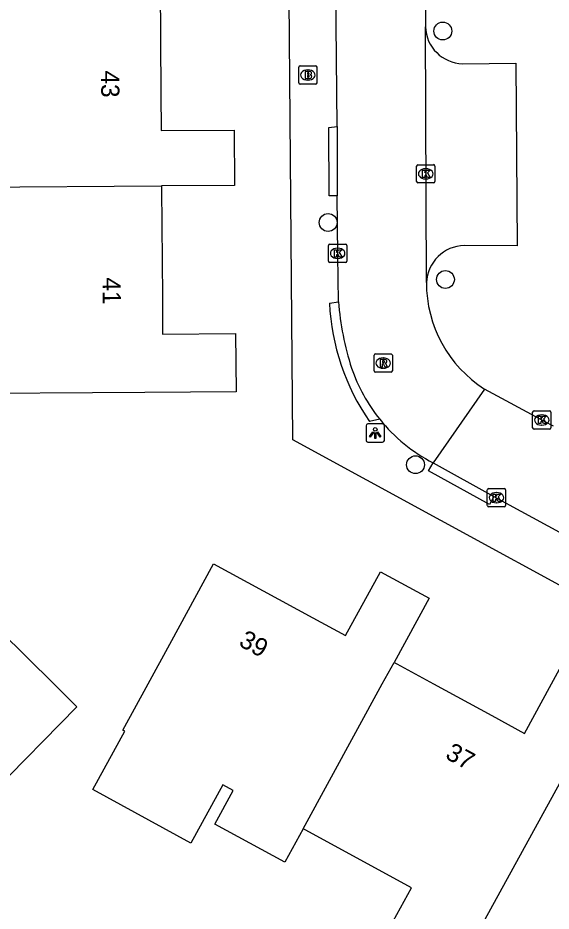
# Model space of a CAD drawing. Extents: x 157321 to 158827, y 386650 to 388532.
# Drawn here: x 157916.06 to 157945.27, y 387487.55 to 387536.5 of the extents above; entities that cross this region are included whole.
import ezdxf

# ---------------------------------------------------------------- set-up
doc = ezdxf.new("R2010")
doc.units = 0
for name, color, linetype in [('IMGEO_Boom', 7, 'Continuous'), ('IMGEO_Brandkraan', 7, 'Continuous'), ('IMGEO_Kolk', 7, 'Continuous'), ('IMGEO_Lichtpunt', 7, 'Continuous'), ('IMGEO_Pand', 7, 'Continuous'), ('IMGEO_Pand_nummerreeks', 7, 'Continuous'), ('IMGEO_Rijbaan_lokaal_open', 7, 'Continuous'), ('IMGEO_Rioolput', 7, 'Continuous'), ('IMGEO_Voetpad_open', 7, 'Continuous')]:
    doc.layers.add(name, color=color, linetype=linetype)

msp = doc.modelspace()

# ---------------------------------------------------------------- linework, layer by layer
at = {"layer": 'IMGEO_Boom'}
for centre in [(157939.332, 387535.78), (157933.051, 387525.286), (157939.477, 387522.163), (157937.837, 387512.012)]:
    msp.add_circle(centre, 0.489, dxfattribs=at)
at = {"layer": 'IMGEO_Brandkraan'}
for p, q in [((157931.44, 387532.944), (157931.44, 387533.796)), ((157931.515, 387533.87), (157932.367, 387533.87)), ((157931.928, 387533.65), (157931.953, 387533.65)), ((157932.441, 387533.796), (157932.441, 387532.944)), ((157931.951, 387533.09), (157931.926, 387533.09)), ((157932.367, 387532.87), (157931.515, 387532.87))]:
    msp.add_line(p, q, dxfattribs=at)
for points in [[(157931.44, 387532.944), (157931.44, 387533.796)], [(157931.515, 387533.87), (157932.367, 387533.87)], [(157931.788, 387533.57), (157931.788, 387533.17), (157932.001, 387533.17)], [(157932.019, 387533.57), (157931.788, 387533.57)], [(157931.967, 387533.489), (157931.913, 387533.489), (157931.913, 387533.413)], [(157932.441, 387533.796), (157932.441, 387532.944)], [(157931.913, 387533.413), (157931.966, 387533.413)], [(157931.975, 387533.337), (157931.913, 387533.337), (157931.913, 387533.256)], [(157931.913, 387533.256), (157931.975, 387533.256)], [(157932.367, 387532.87), (157931.515, 387532.87)]]:
    msp.add_lwpolyline(points, dxfattribs=at)
for centre, radius, start, end in [((157931.517, 387533.794), 0.0765, 91.552, 178.448), ((157931.517, 387533.794), 0.0765, 91.552, 178.448), ((157931.968, 387533.451), 0.0379, 267.8285, 90.9355), ((157932.023, 387533.425), 0.145, 59.4692, 91.5367), ((157932.048, 387533.472), 0.0922, 285.5137, 58.1501), ((157932.365, 387533.794), 0.0765, 1.552, 88.448), ((157932.365, 387533.794), 0.0765, 1.552, 88.448), ((157931.976, 387533.296), 0.0404, 269.8759, 90.5077), ((157932.007, 387533.421), 0.251, 268.6676, 293.5347), ((157932.053, 387533.28), 0.105, 301.3115, 78.989), ((157931.517, 387532.946), 0.0765, 181.552, 268.448), ((157931.517, 387532.946), 0.0765, 181.552, 268.448), ((157932.365, 387532.946), 0.0765, 271.552, 358.448), ((157932.365, 387532.946), 0.0765, 271.552, 358.448)]:
    msp.add_arc(centre, radius, start, end, dxfattribs=at)
for centre, major_axis, ratio, start_param, end_param in [((157931.927, 387533.37), (-0.387, 0.002), 0.722429, 4.712389, 7.853982), ((157931.952, 387533.37), (-0.39, 0.002), 0.717154, 1.570796, 4.712389)]:
    msp.add_ellipse(centre, major_axis=major_axis, ratio=ratio, start_param=start_param, end_param=end_param, dxfattribs=at)
at = {"layer": 'IMGEO_Kolk'}
for p, q in [((157937.897, 387527.53), (157937.897, 387528.382)), ((157937.972, 387528.456), (157938.824, 387528.456)), ((157938.385, 387528.236), (157938.41, 387528.236)), ((157938.898, 387528.382), (157938.898, 387527.53)), ((157938.408, 387527.676), (157938.383, 387527.676)), ((157938.824, 387527.456), (157937.972, 387527.456)), ((157933.072, 387523.17), (157933.072, 387524.022)), ((157933.147, 387524.096), (157933.999, 387524.096)), ((157933.56, 387523.876), (157933.585, 387523.876)), ((157934.073, 387524.022), (157934.073, 387523.17)), ((157933.583, 387523.316), (157933.558, 387523.316)), ((157933.999, 387523.096), (157933.147, 387523.096)), ((157944.254, 387514.039), (157944.254, 387514.891)), ((157944.329, 387514.965), (157945.181, 387514.965)), ((157945.255, 387514.891), (157945.255, 387514.039)), ((157944.742, 387514.745), (157944.767, 387514.745)), ((157945.181, 387513.965), (157944.329, 387513.965)), ((157944.765, 387514.185), (157944.74, 387514.185)), ((157941.772, 387509.78), (157941.772, 387510.632)), ((157941.847, 387510.706), (157942.699, 387510.706)), ((157942.26, 387510.486), (157942.285, 387510.486)), ((157942.773, 387510.632), (157942.773, 387509.78)), ((157942.699, 387509.706), (157941.847, 387509.706)), ((157942.283, 387509.926), (157942.258, 387509.926))]:
    msp.add_line(p, q, dxfattribs=at)
for points in [[(157937.897, 387527.53), (157937.897, 387528.382)], [(157937.972, 387528.456), (157938.824, 387528.456)], [(157938.218, 387528.156), (157938.341, 387528.156), (157938.341, 387528.005), (157938.471, 387528.156), (157938.635, 387528.156), (157938.489, 387528.005), (157938.642, 387527.756), (157938.49, 387527.756), (157938.405, 387527.92), (157938.341, 387527.853), (157938.341, 387527.756), (157938.218, 387527.756), (157938.218, 387528.156)], [(157938.898, 387528.382), (157938.898, 387527.53)], [(157938.824, 387527.456), (157937.972, 387527.456)], [(157933.072, 387523.17), (157933.072, 387524.022)], [(157933.147, 387524.096), (157933.999, 387524.096)], [(157933.393, 387523.796), (157933.516, 387523.796), (157933.516, 387523.645), (157933.646, 387523.796), (157933.81, 387523.796), (157933.664, 387523.645), (157933.817, 387523.396), (157933.665, 387523.396), (157933.58, 387523.56), (157933.516, 387523.493), (157933.516, 387523.396), (157933.393, 387523.396), (157933.393, 387523.796)], [(157934.073, 387524.022), (157934.073, 387523.17)], [(157933.999, 387523.096), (157933.147, 387523.096)], [(157944.254, 387514.039), (157944.254, 387514.891)], [(157944.329, 387514.965), (157945.181, 387514.965)], [(157945.255, 387514.891), (157945.255, 387514.039)], [(157944.575, 387514.665), (157944.698, 387514.665), (157944.698, 387514.514), (157944.828, 387514.665), (157944.992, 387514.665), (157944.846, 387514.514), (157944.999, 387514.265), (157944.847, 387514.265), (157944.762, 387514.429), (157944.698, 387514.362), (157944.698, 387514.265), (157944.575, 387514.265), (157944.575, 387514.665)], [(157945.181, 387513.965), (157944.329, 387513.965)], [(157941.772, 387509.78), (157941.772, 387510.632)], [(157941.847, 387510.706), (157942.699, 387510.706)], [(157942.773, 387510.632), (157942.773, 387509.78)], [(157942.093, 387510.406), (157942.216, 387510.406), (157942.216, 387510.255), (157942.346, 387510.406), (157942.51, 387510.406), (157942.364, 387510.255), (157942.517, 387510.006), (157942.365, 387510.006), (157942.28, 387510.17), (157942.216, 387510.103), (157942.216, 387510.006), (157942.093, 387510.006), (157942.093, 387510.406)], [(157942.699, 387509.706), (157941.847, 387509.706)]]:
    msp.add_lwpolyline(points, dxfattribs=at)
for centre, start, end in [((157937.974, 387528.38), 91.552, 178.448), ((157937.974, 387528.38), 91.552, 178.448), ((157938.822, 387528.38), 1.552, 88.448), ((157938.822, 387528.38), 1.552, 88.448), ((157937.974, 387527.532), 181.552, 268.448), ((157937.974, 387527.532), 181.552, 268.448), ((157938.822, 387527.532), 271.552, 358.448), ((157938.822, 387527.532), 271.552, 358.448), ((157933.149, 387524.02), 91.552, 178.448), ((157933.149, 387524.02), 91.552, 178.448), ((157933.997, 387524.02), 1.552, 88.448), ((157933.997, 387524.02), 1.552, 88.448), ((157933.149, 387523.172), 181.552, 268.448), ((157933.149, 387523.172), 181.552, 268.448), ((157933.997, 387523.172), 271.552, 358.448), ((157933.997, 387523.172), 271.552, 358.448), ((157944.331, 387514.889), 91.552, 178.448), ((157944.331, 387514.889), 91.552, 178.448), ((157945.179, 387514.889), 1.552, 88.448), ((157945.179, 387514.889), 1.552, 88.448), ((157944.331, 387514.041), 181.552, 268.448), ((157944.331, 387514.041), 181.552, 268.448), ((157945.179, 387514.041), 271.552, 358.448), ((157945.179, 387514.041), 271.552, 358.448), ((157941.849, 387510.63), 91.552, 178.448), ((157941.849, 387510.63), 91.552, 178.448), ((157942.697, 387510.63), 1.552, 88.448), ((157942.697, 387510.63), 1.552, 88.448), ((157941.849, 387509.782), 181.552, 268.448), ((157941.849, 387509.782), 181.552, 268.448), ((157942.697, 387509.782), 271.552, 358.448), ((157942.697, 387509.782), 271.552, 358.448)]:
    msp.add_arc(centre, 0.0765, start, end, dxfattribs=at)
for centre, major_axis, ratio, start_param, end_param in [((157938.384, 387527.956), (-0.387, 0.002), 0.722429, 4.712389, 7.853982), ((157938.409, 387527.956), (-0.39, 0.002), 0.717154, 1.570796, 4.712389), ((157933.559, 387523.596), (-0.387, 0.002), 0.722429, 4.712389, 7.853982), ((157933.584, 387523.596), (-0.39, 0.002), 0.717154, 1.570796, 4.712389), ((157944.741, 387514.465), (-0.387, 0.002), 0.722429, 4.712389, 7.853982), ((157944.766, 387514.465), (-0.39, 0.002), 0.717154, 1.570796, 4.712389), ((157942.259, 387510.206), (-0.387, 0.002), 0.722429, 4.712389, 7.853982), ((157942.284, 387510.206), (-0.39, 0.002), 0.717154, 1.570796, 4.712389)]:
    msp.add_ellipse(centre, major_axis=major_axis, ratio=ratio, start_param=start_param, end_param=end_param, dxfattribs=at)
at = {"layer": 'IMGEO_Lichtpunt'}
for p, q in [((157935.135, 387514.153), (157935.135, 387513.346)), ((157935.135, 387514.153), (157935.135, 387513.346)), ((157936.037, 387514.248), (157935.229, 387514.248)), ((157936.037, 387514.248), (157935.229, 387514.248)), ((157936.131, 387513.346), (157936.131, 387514.153)), ((157936.131, 387513.346), (157936.131, 387514.153)), ((157935.229, 387513.252), (157936.037, 387513.252)), ((157935.229, 387513.252), (157936.037, 387513.252))]:
    msp.add_line(p, q, dxfattribs=at)
for points in [[(157935.509, 387513.817), (157935.548, 387513.789), (157935.36, 387513.527), (157935.322, 387513.554), (157935.509, 387513.817)], [(157935.611, 387513.769), (157935.658, 387513.769), (157935.658, 387513.447), (157935.611, 387513.447), (157935.611, 387513.769)], [(157935.721, 387513.789), (157935.759, 387513.816), (157935.946, 387513.554), (157935.907, 387513.526), (157935.721, 387513.789)]]:
    msp.add_lwpolyline(points, dxfattribs=at)
msp.add_circle((157935.634, 387513.951), 0.0994, dxfattribs=at)
for centre, start, end in [((157935.229, 387514.153), 90, 180), ((157935.229, 387514.153), 90, 180), ((157936.037, 387514.153), 0, 90), ((157936.037, 387514.153), 0, 90), ((157935.229, 387513.346), 180, 270), ((157935.229, 387513.346), 180, 270), ((157936.037, 387513.346), 270, 0), ((157936.037, 387513.346), 270, 360)]:
    msp.add_arc(centre, 0.0946, start, end, dxfattribs=at)
at = {"layer": 'IMGEO_Pand'}
for points in [[(157923.853, 387538.443), (157923.854, 387538.281), (157923.895, 387532.364), (157923.909, 387530.327), (157927.911, 387530.355), (157927.922, 387527.318), (157923.923, 387527.292)], [(157923.923, 387527.292), (157923.924, 387527.127), (157923.971, 387521.205), (157923.987, 387519.168), (157927.986, 387519.2), (157928.013, 387516.004), (157923.014, 387515.972), (157911.513, 387515.897), (157911.487, 387520.445), (157913.586, 387520.457), (157913.548, 387527.064), (157913.547, 387527.226)], [(157913.547, 387527.226), (157923.923, 387527.292)], [(157907.31, 387507.639), (157907.42, 387507.53), (157912.114, 387502.889), (157913.589, 387504.38), (157918.019, 387500), (157919.291, 387498.742), (157914.656, 387494.023), (157911.152, 387490.455), (157910.965, 387490.641), (157911.601, 387491.299), (157909.221, 387493.491), (157908.679, 387492.897), (157905.655, 387495.884), (157905.051, 387495.294), (157904.37, 387495.965), (157900.277, 387500), (157900.03, 387500.243)], [(157931.688, 387492.068), (157930.684, 387490.23), (157926.848, 387492.324), (157927.852, 387494.163), (157927.287, 387494.471), (157925.529, 387491.267), (157920.164, 387494.21), (157921.917, 387497.404), (157921.801, 387497.467), (157923.184, 387500), (157924.378, 387502.187), (157926.774, 387506.575), (157932.219, 387503.617), (157934.003, 387502.647), (157935.918, 387506.142), (157938.583, 387504.693), (157936.664, 387501.18)], [(157931.688, 387492.068), (157936.02, 387500), (157936.664, 387501.18)], [(157936.664, 387501.18), (157936.809, 387501.101), (157938.83, 387500), (157942.014, 387498.265), (157943.803, 387497.291), (157945.279, 387500), (157945.718, 387500.806), (157947.208, 387500), (157948.381, 387499.365), (157946.458, 387495.859)], [(157941.457, 387486.738), (157946.458, 387495.859)], [(157941.457, 387486.738), (157940.448, 387484.898), (157936.612, 387486.992), (157937.616, 387488.831), (157931.828, 387491.992), (157931.688, 387492.068)]]:
    msp.add_lwpolyline(points, dxfattribs=at)
at = {"layer": 'IMGEO_Rijbaan_lokaal_open'}
for points in [[(157938.384, 387547.602), (157938.4, 387545.383), (157938.378, 387536.008)], [(157933.54, 387530.546), (157933.482, 387538.043)], [(157938.433, 387521.992), (157938.378, 387536.008)], [(157933.54, 387530.546), (157933.544, 387526.75)], [(157933.622, 387520.947), (157933.575, 387523.499), (157933.544, 387526.75)], [(157941.618, 387516.158), (157938.798, 387512.117)], [(157945.392, 387514.117), (157944.896, 387514.387), (157941.618, 387516.158)], [(157938.798, 387512.117), (157942.132, 387510.273)], [(157942.132, 387510.273), (157948.676, 387506.705)]]:
    msp.add_lwpolyline(points, dxfattribs=at)
for centre, radius, start, end in [((157945.36, 387521.987), 6.927, 179.9592, 237.3044), ((157948.57, 387521.999), 14.985, 184.0275, 198.2408), ((157942.993, 387520.236), 9.137, 198.6823, 218.853), ((157942.983, 387520.215), 9.116, 218.7963, 242.6741)]:
    msp.add_arc(centre, radius, start, end, dxfattribs=at)
at = {"layer": 'IMGEO_Rioolput'}
for p, q in [((157935.569, 387517.156), (157935.569, 387518.008)), ((157935.644, 387518.082), (157936.496, 387518.082)), ((157936.057, 387517.862), (157936.082, 387517.862)), ((157936.57, 387518.008), (157936.57, 387517.156)), ((157936.496, 387517.082), (157935.644, 387517.082)), ((157936.08, 387517.302), (157936.055, 387517.302))]:
    msp.add_line(p, q, dxfattribs=at)
for points in [[(157935.569, 387517.156), (157935.569, 387518.008)], [(157935.644, 387518.082), (157936.496, 387518.082)], [(157936.57, 387518.008), (157936.57, 387517.156)], [(157936.158, 387517.78), (157935.906, 387517.782), (157935.906, 387517.382)], [(157935.906, 387517.382), (157936.03, 387517.382), (157936.03, 387517.544), (157936.041, 387517.544)], [(157936.084, 387517.701), (157936.03, 387517.701), (157936.03, 387517.62)], [(157936.03, 387517.62), (157936.082, 387517.62)], [(157936.088, 387517.515), (157936.159, 387517.382), (157936.299, 387517.382), (157936.234, 387517.508)], [(157936.496, 387517.082), (157935.644, 387517.082)]]:
    msp.add_lwpolyline(points, dxfattribs=at)
for centre, radius, start, end in [((157935.646, 387518.006), 0.0765, 91.552, 178.448), ((157935.646, 387518.006), 0.0765, 91.552, 178.448), ((157936.494, 387518.006), 0.0765, 1.552, 88.448), ((157936.494, 387518.006), 0.0765, 1.552, 88.448), ((157936.04, 387517.491), 0.0533, 26.0293, 88.6989), ((157936.066, 387517.809), 0.19, 274.7715, 282.9687), ((157936.09, 387517.605), 0.0964, 77.0061, 93.1865), ((157936.104, 387517.662), 0.0378, 276.6634, 79.6772), ((157936.157, 387517.67), 0.109, 350.3612, 89.416), ((157936.155, 387517.67), 0.112, 277.5842, 350.9817), ((157936.139, 387517.455), 0.108, 29.5134, 73.7905), ((157935.646, 387517.158), 0.0765, 181.552, 268.448), ((157935.646, 387517.158), 0.0765, 181.552, 268.448), ((157936.494, 387517.158), 0.0765, 271.552, 358.448), ((157936.494, 387517.158), 0.0765, 271.552, 358.448)]:
    msp.add_arc(centre, radius, start, end, dxfattribs=at)
for centre, major_axis, ratio, start_param, end_param in [((157936.056, 387517.582), (-0.387, 0.002), 0.722429, 4.712389, 7.853982), ((157936.081, 387517.582), (-0.39, 0.002), 0.717154, 1.570796, 4.712389)]:
    msp.add_ellipse(centre, major_axis=major_axis, ratio=ratio, start_param=start_param, end_param=end_param, dxfattribs=at)
at = {"layer": 'IMGEO_Voetpad_open'}
for points in [[(158026.142, 387481.499), (158021.016, 387481.457), (158000, 387481.305), (157990.079, 387481.233), (157962.562, 387496.218), (157955.633, 387500), (157931.114, 387513.382), (157930.704, 387563.922), (157930.223, 387563.93), (157929.973, 387592.849)], [(157940.416, 387533.991), (157943.342, 387534.021), (157943.407, 387524.014), (157940.509, 387524.031)], [(157933.544, 387526.75), (157933.105, 387526.745), (157933.09, 387530.501), (157933.54, 387530.546)], [(157933.126, 387520.872), (157933.622, 387520.947)], [(157935.878, 387514.504), (157935.314, 387514.39)], [(157942.132, 387510.273), (157941.891, 387509.836), (157938.557, 387511.68), (157938.798, 387512.117)]]:
    msp.add_lwpolyline(points, dxfattribs=at)
for centre, radius, start, end in [((157940.47, 387536.083), 2.093, 182.06, 268.5335), ((157940.577, 387521.885), 2.147, 91.8212, 177.1485), ((157945.532, 387521.449), 12.42, 182.6648, 214.6394)]:
    msp.add_arc(centre, radius, start, end, dxfattribs=at)

# ---------------------------------------------------------------- texts
at = {"layer": 'IMGEO_Pand_nummerreeks'}
for s, rotation, p in [('43', 270.3894, (157920.612, 387533.618)), ('41', 270.3894, (157920.689, 387522.281)), ('39', 331.4839, (157928.096, 387502.123)), ('37', 331.4438, (157939.412, 387495.95))]:
    msp.add_text(s, height=1, rotation=rotation, dxfattribs=at).set_placement(p)

doc.saveas('drawing.dxf')
